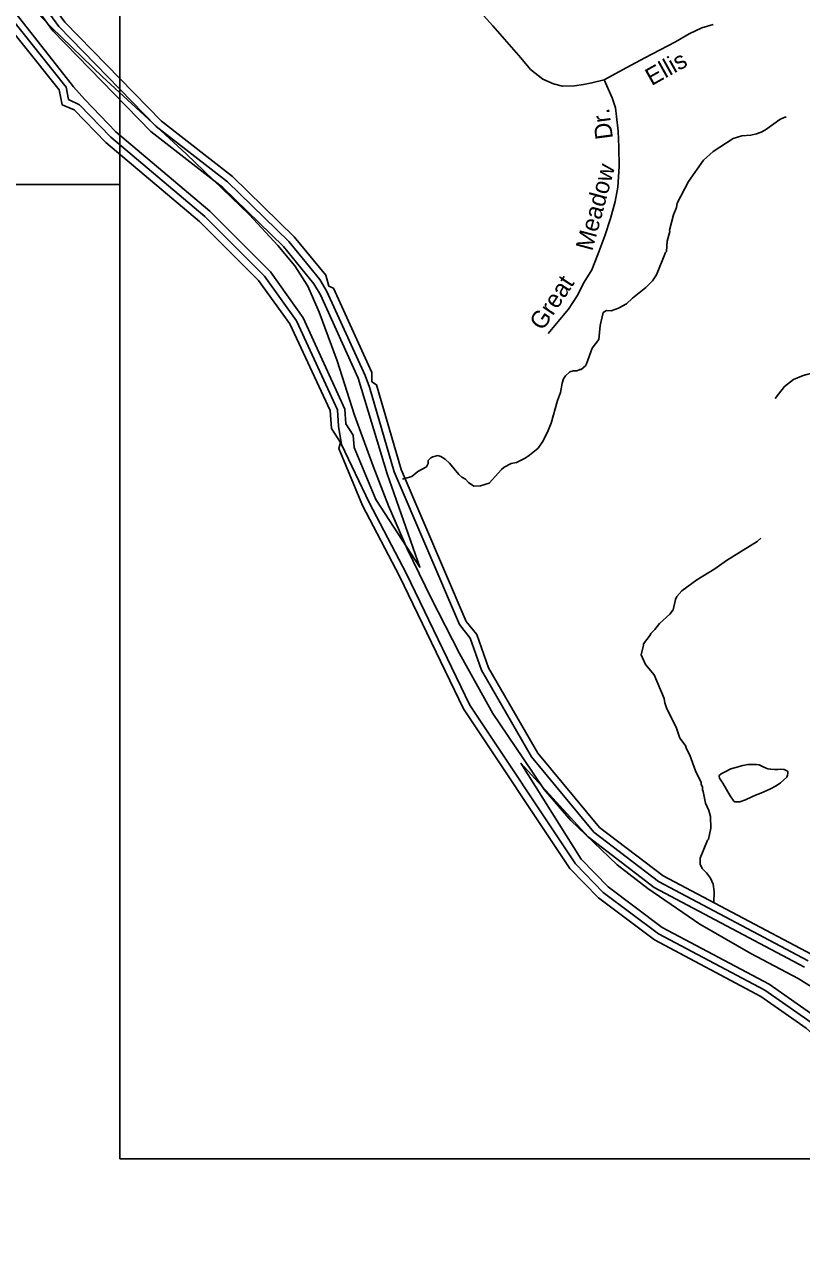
# Model space of a CAD drawing. Extents: x 1547597 to 1699558, y 810033 to 920809.
# Drawn here: x 1570690 to 1574920, y 830743 to 837485 of the extents above; entities that cross this region are included whole.
import ezdxf

# ---------------------------------------------------------------- set-up
doc = ezdxf.new("R2010")
doc.units = 0
for name, color, linetype in [('Exist Boundary Political CountyLine', 7, 'Continuous'), ('Exist Hydrographic Bay Label', 7, 'Continuous'), ('Exist Hydrographic Buffer Line', 7, 'Continuous'), ('Exist Hydrographic Misc Water Feature', 7, 'Continuous'), ('Exist Road Non-System Type 51', 7, 'Continuous'), ('Exist Road Non-System Type 51 Label', 7, 'Continuous'), ('Exist Road Secondary Type 51 Attributed', 7, 'Continuous'), ('Exist Road Secondary Type 51 Label', 7, 'Continuous'), ('Map Preparation Inset Cut Line', 7, 'Continuous')]:
    doc.layers.add(name, color=color, linetype=linetype)

msp = doc.modelspace()

# ---------------------------------------------------------------- linework, layer by layer
at = {"layer": 'Exist Boundary Political CountyLine'}
for points in [[(1570639.2, 837677.3), (1570835.6, 837469.7), (1571113.7, 837200.3), (1571568.4, 836780.7)], [(1571568.4, 836780.7), (1571915, 836449.5), (1572069.5, 836281.6), (1572162.2, 836171.2), (1572232.8, 836060.8), (1572294.6, 835919.4), (1572391.7, 835654.4), (1572486.7, 835358.5), (1572588.2, 835080.3), (1572672.1, 834863.8), (1572773.6, 834629.7), (1572903.8, 834360.3), (1573058.3, 834060), (1573239.3, 833733.1), (1573402.7, 833490.2), (1573519.6, 833317.9), (1573665.3, 833150.1), (1573788.9, 833030.9), (1573917, 832907.2), (1574084.7, 832779.1), (1574367.2, 832584.8), (1574645.3, 832425.8), (1574903.6, 832288.8), (1575102.3, 832165.2)]]:
    msp.add_lwpolyline(points, dxfattribs=at)
at = {"layer": 'Exist Hydrographic Bay Label'}
for points in [[(1570893.5, 837048.3), (1570877.5, 837130.7), (1570255.4, 837908.1)], [(1576500.5, 831022.5), (1576343.5, 831134), (1575283.5, 832215.8), (1574978.5, 832419), (1574167.5, 832849), (1573820.5, 833112.1), (1573485.5, 833516.1), (1573216.5, 833981.1), (1573152.5, 834162.9), (1573095.5, 834233.1), (1572740.5, 835060.9), (1572605.5, 835523.3), (1572580.5, 835540.2), (1572581.4, 835589.4), (1572371.5, 836049.9), (1572346.4, 836060.3), (1572330.5, 836119.7), (1572158.5, 836330), (1571821.5, 836658.5), (1571434.5, 836958.5), (1570908.5, 837497.8), (1570744.5, 837724.2)], [(1576204.5, 830743), (1576188.5, 830818.8), (1575836.5, 831223.1), (1574947.5, 832019.1), (1574699.5, 832191.6), (1574120.5, 832498.7), (1573815.4, 832728.1), (1573659.5, 832888.9), (1573080.5, 833757.4), (1572731.4, 834480.1), (1572529.5, 834864.9), (1572400.5, 835176.2), (1572409.5, 835208.8), (1572360.5, 835285.3), (1572353.5, 835383.9), (1572134.5, 835854.5), (1571963.5, 836091), (1571642.5, 836412.6), (1571132.4, 836843.2), (1570959.5, 837020.7), (1570893.5, 837048.3)]]:
    msp.add_lwpolyline(points, dxfattribs=at)
at = {"layer": 'Exist Hydrographic Buffer Line'}
for points in [[(1574974.2, 832048.9), (1574722.4, 832224.4), (1574142, 832532.6), (1573842, 832758.2), (1573690.8, 832914.1), (1573115.4, 833777.2), (1572767.4, 834497.4), (1572565.8, 834881.9), (1572416.3, 835197.9), (1572399.7, 835298.3), (1572393.4, 835386.8), (1572170.8, 835871.4), (1571995.9, 836114.4), (1571670.8, 836440.9), (1571159.7, 836872.6), (1570988.1, 837048.6), (1570928.6, 837076.9), (1570915.1, 837144.4), (1570288.9, 837930.4)], [(1570683, 837672.8), (1570843.7, 837450.9), (1571377.2, 836902.6), (1571768.9, 836598.1), (1572099.5, 836275.9), (1572264.6, 836073.8), (1572300.4, 836013), (1572507.3, 835559), (1572663.7, 835038.5), (1572843.1, 834528.8), (1572601.9, 834898.9), (1572485, 835181.4), (1572478.8, 835248.8), (1572438.8, 835311.3), (1572433.3, 835389.6), (1572207, 835888.3), (1572028.3, 836137.9), (1571699.1, 836469.1), (1571187, 836901.9), (1571016.8, 837076.5), (1570956, 837145.9), (1570322.3, 837952.6)], [(1570713.7, 837698.5), (1570876.1, 837474.3), (1571405.9, 836930.6), (1571795.3, 836628.3), (1572129, 836303), (1572297.5, 836096.8), (1572335.9, 836031.4), (1572544.4, 835574.2), (1572567.5, 835510.8), (1572702, 835049.7), (1573058.7, 834217.3), (1573117, 834143.1), (1573178.8, 833967.8), (1573450.9, 833496.1), (1573789.7, 833086.6), (1574143.3, 832817.1), (1574958, 832384.6)], [(1575001, 832078.7), (1574745.1, 832257.2), (1574163.5, 832566.4), (1573868.6, 832788.3), (1573722, 832939.3), (1573392.8, 833461.2), (1573758.8, 833061), (1574119.2, 832785.3), (1574937.5, 832350.2)]]:
    msp.add_lwpolyline(points, dxfattribs=at)
at = {"layer": 'Exist Hydrographic Misc Water Feature'}
for points in [[(1574838.2, 836980.6), (1574830.2, 836980.7), (1574804.1, 836969), (1574725.5, 836912), (1574701.3, 836900.3), (1574677.2, 836890.7), (1574645.1, 836883.1), (1574597.1, 836879.7), (1574548.9, 836864.3), (1574440, 836793.7), (1574387.8, 836746), (1574306.1, 836631.4), (1574244.8, 836512.3), (1574240.5, 836488.3), (1574224, 836448.6), (1574203, 836364.8), (1574203.7, 836357.9), (1574190.4, 836305), (1574185.7, 836249.1), (1574180.1, 836244.5), (1574132.1, 836121.9), (1574109.8, 836090.1), (1574073.4, 836052.6), (1574000.7, 835995.5), (1573967.9, 835963.5), (1573924.7, 835941.3), (1573884.2, 835926.7), (1573859, 835927), (1573841.8, 835917.6), (1573825, 835845.8), (1573818.1, 835769.9), (1573781.5, 835722.4), (1573750.5, 835636.9), (1573744.4, 835627), (1573722.1, 835607.2), (1573714.1, 835607.3), (1573698.1, 835599.5), (1573678.1, 835599.8), (1573660, 835594), (1573635.7, 835572.3), (1573625.6, 835556.5), (1573617.3, 835532.6), (1573608.6, 835480.7), (1573592.1, 835436.9), (1573558.7, 835313.4), (1573542.2, 835273.7), (1573513.6, 835218), (1573487.2, 835178.4), (1573440.7, 835139), (1573416.5, 835123.3), (1573368.2, 835099.9), (1573340.5, 835093.8), (1573302.5, 835074.1), (1573287.2, 835061.7), (1573220.8, 834986.9), (1573172.7, 834972.4), (1573137.4, 834970.3), (1573107.4, 834990.8), (1573091.6, 835008.2), (1573071.3, 835019.7), (1573055.5, 835033.9), (1573004.3, 835096.5), (1572980.6, 835118.7), (1572956.7, 835133), (1572940.8, 835137.3), (1572912.7, 835131.6), (1572902.7, 835125.8), (1572888.4, 835109.9), (1572888.3, 835093.9), (1572878, 835076.1), (1572831.7, 835050.7), (1572799.4, 835023.1), (1572747.6, 835009.6)], [(1574701.1, 834687.4), (1574680.9, 834669.6), (1574513.6, 834565.8), (1574449.9, 834519.7), (1574352.4, 834459.8), (1574269.7, 834400.9), (1574243.4, 834369.2), (1574235.2, 834353.3), (1574222.6, 834297.5), (1574204.2, 834273.8), (1574147.6, 834222.5), (1574123.3, 834190.8), (1574101, 834169.1), (1574096.9, 834159.2), (1574060.4, 834111.6), (1574061.5, 834105.5), (1574047.7, 834051.9), (1574071, 833999.6), (1574118.3, 833943), (1574172.8, 833814.4), (1574176.5, 833790.3), (1574188.1, 833758.2), (1574239, 833657.6), (1574258.3, 833597.4), (1574293.7, 833553), (1574292.5, 833547.5), (1574313.1, 833504.7), (1574344.1, 833420.4), (1574375.3, 833356), (1574375.2, 833348), (1574383, 833331.9), (1574382.8, 833316), (1574386.7, 833307.9), (1574398, 833243.8), (1574417.5, 833203.6), (1574425.2, 833171.5), (1574428.3, 833107.5), (1574415.6, 833047.7), (1574409.6, 833043.1), (1574370.4, 832944.3), (1574370.1, 832912.3), (1574379.7, 832888.2), (1574403.5, 832863.9), (1574425.2, 832835.6), (1574440.7, 832803.5), (1574446.3, 832763.4), (1574443.5, 832701.2)], [(1574506.7, 833415.2), (1574535.9, 833431), (1574556.5, 833437), (1574602.5, 833449.3), (1574629.5, 833454.1), (1574649.5, 833455.3), (1574676.4, 833455.3), (1574690.5, 833453), (1574709.9, 833444.2), (1574728.6, 833434.3), (1574738.6, 833431.6), (1574753.9, 833428.7), (1574775.4, 833427.2), (1574792.2, 833427.9), (1574808.6, 833428.7), (1574827.5, 833427.3), (1574835.4, 833424.6), (1574844.7, 833419.1), (1574847.8, 833414.9), (1574848.2, 833406.9), (1574846.4, 833396.5), (1574841, 833385.5), (1574826, 833370.5), (1574807.3, 833354), (1574783.9, 833338.1), (1574749.4, 833319.8), (1574700.5, 833299.1), (1574671.3, 833287.5), (1574651.7, 833277.8), (1574616.7, 833262.7), (1574585.4, 833250.6), (1574570.1, 833250.4), (1574559.2, 833251.1), (1574552.4, 833255.4), (1574533.8, 833283.1), (1574512.4, 833319.3), (1574493.4, 833352.3), (1574475, 833381), (1574473, 833390.6), (1574474.8, 833395.8), (1574483.8, 833403), (1574506.7, 833415.2)]]:
    msp.add_lwpolyline(points, dxfattribs=at)
at = {"layer": 'Exist Road Non-System Type 51'}
for points in [[(1573542.3, 835803.2), (1573605.4, 835878.4), (1573652.2, 835935.7), (1573699.3, 836006.9), (1573738.4, 836082.4), (1573779.4, 836149.8), (1573812.7, 836233.4), (1573850.2, 836334.9), (1573881.5, 836428.5), (1573906.8, 836522.2), (1573922, 836600), (1573927.7, 836711.9), (1573927.2, 836818), (1573922.4, 836904.1), (1573913.6, 836984.4), (1573908.4, 837032.5), (1573891.1, 837086.7), (1573846.4, 837185.4)], [(1575206.4, 835617), (1575150.4, 835613.8), (1575086.2, 835608.7), (1574997.9, 835592), (1574931.6, 835573), (1574877.3, 835551.6), (1574828.7, 835514.4), (1574796, 835472.8), (1574777.7, 835449)]]:
    msp.add_lwpolyline(points, dxfattribs=at)
at = {"layer": 'Exist Road Secondary Type 51 Attributed'}
msp.add_lwpolyline([(1574440.5, 837485.7), (1574378.5, 837468), (1574309.8, 837434.3), (1574235.2, 837391.4), (1574068.2, 837304.2), (1573969.4, 837251.6), (1573846.4, 837185.4), (1573779.8, 837167.6), (1573734.7, 837159.2), (1573685.3, 837151.9), (1573620.2, 837149.8), (1573570.8, 837162.4), (1573512, 837187.6), (1573445.8, 837241.2), (1573393.3, 837304.2), (1573239.3, 837478.3), (1573188.8, 837535.6)], dxfattribs=at)
at = {"layer": 'Map Preparation Inset Cut Line'}
for points in [[(1633724, 874749.3), (1571208, 874749.3), (1571208, 831307.2), (1633724, 831307.2)], [(1571208, 866094.1), (1551164.8, 866094.1), (1551164.8, 836614), (1571208, 836614)]]:
    msp.add_lwpolyline(points, close=True, dxfattribs=at)

# ---------------------------------------------------------------- texts
at = {"layer": 'Exist Road Non-System Type 51 Label'}
for s, rotation, p in [('Dr.', 97.5417, (1573895.1, 836865.9)), ('Meadow', 74.88893, (1573781.7, 836248)), ('Great', 56.51208, (1573512.2, 835813.3))]:
    msp.add_text(s, height=95, rotation=rotation, dxfattribs=at).set_placement(p)
at = {"layer": 'Exist Road Secondary Type 51 Label'}
msp.add_text('Ellis', height=95, rotation=29.20817, dxfattribs=at).set_placement((1574104.9, 837149.9))

doc.saveas('drawing.dxf')
